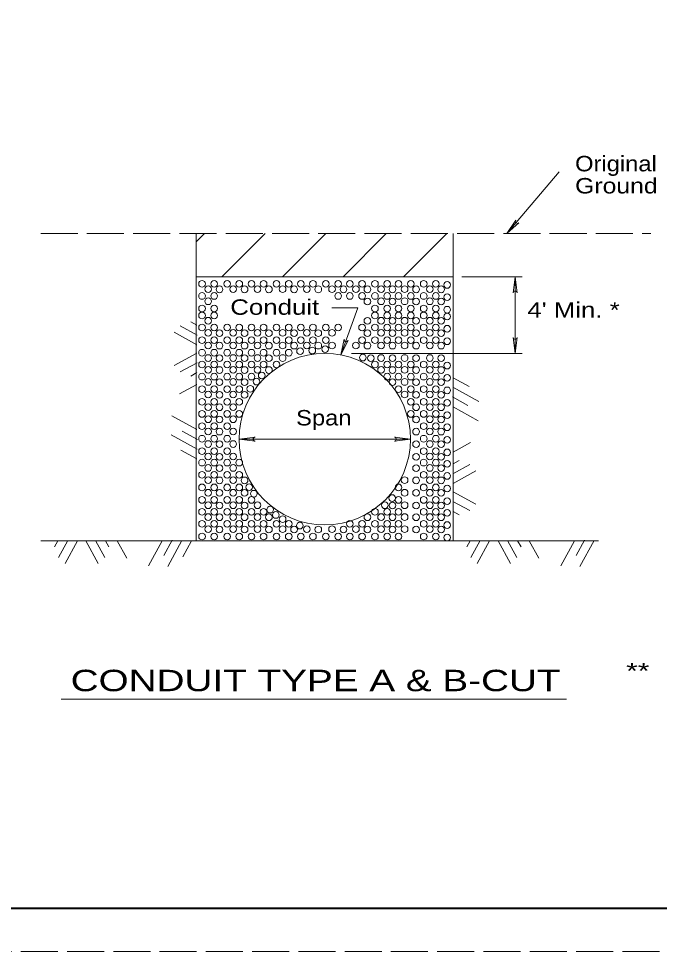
# Model space of a CAD drawing. Extents: x 750.7 to 784.7, y 834.8 to 878.8.
# Drawn here: x 763.05 to 770.52, y 834.78 to 845.67 of the extents above; entities that cross this region are included whole.
import ezdxf

# ---------------------------------------------------------------- set-up
doc = ezdxf.new("R2010")
doc.units = 0
doc.header["$LTSCALE"] = 0.072
doc.linetypes.add('LONG_DASHED', pattern=[7.5, 6, -1.5])
doc.layers.add('1', color=7, linetype='Continuous', lineweight=13)
doc.layers.add('47', color=7, linetype='Continuous', lineweight=13)

msp = doc.modelspace()

# ---------------------------------------------------------------- linework, layer by layer
at = {"layer": '1'}
for p, q in [((768.74392, 843.15875), (769.355, 843.88067)), ((765.11817, 843.15875), (765.11817, 839.5755)), ((765.11817, 843.06225), (765.21467, 843.15875)), ((765.41725, 842.65417), (765.92175, 843.15875)), ((766.12433, 842.65417), (766.62883, 843.15875)), ((766.83142, 842.65417), (767.33592, 843.15875)), ((767.5385, 842.65417), (768.043, 843.15875)), ((768.11817, 843.15875), (768.11817, 839.5755)), ((765.11817, 842.65417), (768.11817, 842.65417)), ((768.21917, 842.65417), (768.9205, 842.65417)), ((768.84058, 841.76058), (768.84058, 842.65417)), ((765.12775, 841.97533), (764.93225, 842.08317)), ((765.12633, 842.09192), (765.055, 842.13125)), ((765.12383, 841.86325), (764.86125, 842.00817)), ((765.12383, 841.76533), (764.86125, 841.62042)), ((766.93208, 841.76058), (768.9205, 841.76058)), ((765.12775, 841.65325), (764.93225, 841.54542)), ((765.12633, 841.53667), (765.055, 841.49733)), ((765.12683, 841.40033), (764.92275, 841.28775)), ((768.11817, 841.47783), (768.30258, 841.37608)), ((768.11425, 841.36575), (768.41542, 841.19958)), ((768.11033, 841.25375), (768.28875, 841.15533)), ((768.11567, 841.13658), (768.40667, 840.976)), ((765.12633, 840.87317), (764.83533, 841.03375)), ((765.13167, 840.756), (764.95325, 840.85442)), ((765.12775, 840.644), (764.82658, 840.81017)), ((765.61817, 840.76083), (767.61817, 840.76083)), ((768.11517, 840.60942), (768.31925, 840.722)), ((765.12383, 840.53192), (764.93942, 840.63367)), ((768.11567, 840.47308), (768.187, 840.51242)), ((768.11425, 840.3565), (768.30975, 840.46433)), ((768.11817, 840.24442), (768.38075, 840.38933)), ((768.11817, 840.1465), (768.38075, 840.00158)), ((768.11425, 840.03442), (768.30975, 839.92658)), ((768.11567, 839.91783), (768.187, 839.8785)), ((763.30275, 839.5755), (769.81092, 839.5755)), ((763.50333, 839.5755), (763.464, 839.50417)), ((763.61992, 839.57692), (763.51208, 839.38142)), ((763.732, 839.573), (763.58708, 839.31042)), ((763.82992, 839.573), (763.97483, 839.31042)), ((763.942, 839.57692), (764.04983, 839.38142)), ((764.05858, 839.5755), (764.09792, 839.50417)), ((764.19492, 839.576), (764.3075, 839.37192)), ((764.72208, 839.5755), (764.5615, 839.2845)), ((764.83925, 839.58083), (764.74083, 839.40242)), ((764.95125, 839.57692), (764.78508, 839.27575)), ((765.06333, 839.573), (764.96158, 839.38858)), ((768.31375, 839.5755), (768.27442, 839.50417)), ((768.43033, 839.57692), (768.3225, 839.38142)), ((768.54242, 839.573), (768.3975, 839.31042)), ((768.64033, 839.573), (768.78525, 839.31042)), ((768.75242, 839.57692), (768.86025, 839.38142)), ((768.869, 839.5755), (768.90833, 839.50417)), ((769.00533, 839.576), (769.11792, 839.37192)), ((769.5325, 839.5755), (769.37192, 839.2845)), ((769.64967, 839.58083), (769.55125, 839.40242)), ((769.76167, 839.57692), (769.5955, 839.27575)), ((763.54108, 837.72625), (769.44075, 837.72625))]:
    msp.add_line(p, q, dxfattribs=at)
at = {"layer": '1', "linetype": 'LONG_DASHED'}
msp.add_line((763.30275, 843.15875), (770.42208, 843.15875), dxfattribs=at)
at = {"layer": '1', "lineweight": 25}
msp.add_line((784.15083, 835.28433), (752.65083, 835.28433), dxfattribs=at)
at = {"layer": '1', "linetype": 'LONG_DASHED'}
msp.add_lwpolyline([(750.65083, 834.78433), (784.65083, 834.78433), (784.65083, 856.78433), (750.65083, 856.78433)], close=True, dxfattribs=at)
at = {"layer": '1', "lineweight": 40}
for points in [[(784.15083, 835.28433), (752.65083, 835.28433), (752.65083, 856.28433), (784.15083, 856.28433)], [(784.15083, 835.28433), (752.65083, 835.28433), (752.65083, 856.28433)]]:
    msp.add_lwpolyline(points, dxfattribs=at)
at = {"layer": '1'}
msp.add_lwpolyline([(766.69908, 842.29425), (767.00342, 842.29425), (766.80425, 841.74333)], dxfattribs=at)
for centre, radius in [((765.18571, 842.57344), 0.03892), ((765.32774, 842.57347), 0.03892), ((765.47863, 842.57344), 0.03892), ((765.62066, 842.57347), 0.03892), ((765.76271, 842.57344), 0.03892), ((765.90474, 842.57347), 0.03892), ((766.05563, 842.57344), 0.03892), ((766.19766, 842.57347), 0.03892), ((766.33871, 842.57344), 0.03892), ((766.48074, 842.57347), 0.03892), ((766.63163, 842.57344), 0.03892), ((766.77366, 842.57347), 0.03892), ((766.9113, 842.57344), 0.03892), ((767.05333, 842.57347), 0.03892), ((767.20421, 842.57344), 0.03892), ((767.34624, 842.57347), 0.03892), ((767.47946, 842.57344), 0.03892), ((767.62149, 842.57347), 0.03892), ((767.77238, 842.57344), 0.03892), ((767.91441, 842.57347), 0.03892), ((768.04758, 842.56014), 0.03892), ((765.18571, 842.43136), 0.03892), ((765.25674, 842.51131), 0.03892), ((765.32774, 842.43139), 0.03892), ((765.38991, 842.50897), 0.03892), ((765.54966, 842.51131), 0.03892), ((765.68283, 842.50897), 0.03892), ((765.83374, 842.51131), 0.03892), ((765.96691, 842.50897), 0.03892), ((766.12666, 842.51131), 0.03892), ((766.25983, 842.50897), 0.03892), ((766.40974, 842.51131), 0.03892), ((766.54291, 842.50897), 0.03892), ((766.70266, 842.51131), 0.03892), ((766.77366, 842.43139), 0.03892), ((766.83583, 842.50897), 0.03892), ((766.9113, 842.43136), 0.03892), ((766.98233, 842.51131), 0.03892), ((767.05333, 842.43139), 0.03892), ((767.11549, 842.50897), 0.03892), ((767.20421, 842.43136), 0.03892), ((767.27524, 842.51131), 0.03892), ((767.34624, 842.43139), 0.03892), ((767.40841, 842.50897), 0.03892), ((767.47946, 842.43136), 0.03892), ((767.55049, 842.51131), 0.03892), ((767.62149, 842.43139), 0.03892), ((767.68366, 842.50897), 0.03892), ((767.77238, 842.43136), 0.03892), ((767.84341, 842.51131), 0.03892), ((767.91441, 842.43139), 0.03892), ((767.97658, 842.50897), 0.03892), ((765.25674, 842.36922), 0.03892), ((767.11549, 842.36689), 0.03892), ((767.27524, 842.36922), 0.03892), ((767.40841, 842.36689), 0.03892), ((767.55049, 842.36922), 0.03892), ((767.68366, 842.36689), 0.03892), ((767.84341, 842.36922), 0.03892), ((767.97658, 842.36689), 0.03892), ((768.04758, 842.41806), 0.03892), ((765.18571, 842.28486), 0.03892), ((765.18571, 842.20494), 0.03892), ((765.32774, 842.28489), 0.03892), ((765.32774, 842.20497), 0.03892), ((767.20421, 842.28486), 0.03892), ((767.20421, 842.20494), 0.03892), ((767.34624, 842.28489), 0.03892), ((767.34624, 842.20497), 0.03892), ((767.47946, 842.28486), 0.03892), ((767.47946, 842.20494), 0.03892), ((767.62149, 842.28489), 0.03892), ((767.62149, 842.20497), 0.03892), ((767.77238, 842.28486), 0.03892), ((767.77238, 842.20494), 0.03892), ((767.91441, 842.28489), 0.03892), ((767.91441, 842.20497), 0.03892), ((768.04758, 842.27156), 0.03892), ((765.25674, 842.14281), 0.03892), ((767.11549, 842.14047), 0.03892), ((767.27524, 842.14281), 0.03892), ((767.40841, 842.14047), 0.03892), ((767.55049, 842.14281), 0.03892), ((767.68366, 842.14047), 0.03892), ((767.84341, 842.14281), 0.03892), ((767.97658, 842.14047), 0.03892), ((768.04758, 842.19164), 0.03892), ((765.18571, 842.06286), 0.03892), ((765.25674, 842.00072), 0.03892), ((765.32774, 842.06289), 0.03892), ((765.38991, 841.99839), 0.03892), ((765.47863, 842.06286), 0.03892), ((765.54966, 842.00072), 0.03892), ((765.62066, 842.06289), 0.03892), ((765.68283, 841.99839), 0.03892), ((765.76271, 842.06286), 0.03892), ((765.83374, 842.00072), 0.03892), ((765.90474, 842.06289), 0.03892), ((765.96691, 841.99839), 0.03892), ((766.05563, 842.06286), 0.03892), ((766.12666, 842.00072), 0.03892), ((766.19766, 842.06289), 0.03892), ((766.25983, 841.99839), 0.03892), ((766.33871, 842.06286), 0.03892), ((766.40974, 842.00072), 0.03892), ((766.48074, 842.06289), 0.03892), ((766.54291, 841.99839), 0.03892), ((766.63163, 842.06286), 0.03892), ((766.70266, 842.00072), 0.03892), ((766.77366, 842.06289), 0.03892), ((767.05333, 842.06289), 0.03892), ((767.11549, 841.99839), 0.03892), ((767.20421, 842.06286), 0.03892), ((767.27524, 842.00072), 0.03892), ((767.34624, 842.06289), 0.03892), ((767.40841, 841.99839), 0.03892), ((767.47946, 842.06286), 0.03892), ((767.55049, 842.00072), 0.03892), ((767.62149, 842.06289), 0.03892), ((767.68366, 841.99839), 0.03892), ((767.77238, 842.06286), 0.03892), ((767.84341, 842.00072), 0.03892), ((767.91441, 842.06289), 0.03892), ((767.97658, 841.99839), 0.03892), ((768.04758, 842.04956), 0.03892), ((765.18571, 841.91636), 0.03892), ((765.32774, 841.91639), 0.03892), ((765.47863, 841.91636), 0.03892), ((765.62066, 841.91639), 0.03892), ((765.76271, 841.91636), 0.03892), ((765.90474, 841.91639), 0.03892), ((766.05563, 841.91636), 0.03892), ((766.19766, 841.91639), 0.03892), ((766.33871, 841.91636), 0.03892), ((766.48074, 841.91639), 0.03892), ((766.63163, 841.91636), 0.03892), ((767.05333, 841.91639), 0.03892), ((767.20421, 841.91636), 0.03892), ((767.34624, 841.91639), 0.03892), ((767.47946, 841.91636), 0.03892), ((767.62149, 841.91639), 0.03892), ((767.77238, 841.91636), 0.03892), ((767.91441, 841.91639), 0.03892), ((768.04758, 841.90306), 0.03892), ((765.18571, 841.76978), 0.03892), ((765.25674, 841.85422), 0.03892), ((765.32774, 841.76981), 0.03892), ((765.38991, 841.85189), 0.03892), ((765.47863, 841.76978), 0.03892), ((765.54966, 841.85422), 0.03892), ((765.62066, 841.76981), 0.03892), ((765.68283, 841.85189), 0.03892), ((765.76271, 841.76978), 0.03892), ((765.83374, 841.85422), 0.03892), ((765.90474, 841.76981), 0.03892), ((765.96691, 841.85189), 0.03892), ((766.05563, 841.76978), 0.03892), ((766.12666, 841.85422), 0.03892), ((766.19766, 841.76981), 0.03892), ((766.25983, 841.85189), 0.03892), ((766.32981, 841.78758), 0.03892), ((766.40974, 841.85422), 0.03892), ((766.47292, 841.79412), 0.03892), ((766.54291, 841.85189), 0.03892), ((766.62375, 841.81187), 0.03892), ((766.70266, 841.85422), 0.03892), ((766.98233, 841.85422), 0.03892), ((767.11549, 841.85189), 0.03892), ((767.27524, 841.85422), 0.03892), ((767.40841, 841.85189), 0.03892), ((767.55049, 841.85422), 0.03892), ((767.68366, 841.85189), 0.03892), ((767.84341, 841.85422), 0.03892), ((767.97658, 841.85189), 0.03892), ((765.25674, 841.70764), 0.03892), ((765.38991, 841.70531), 0.03892), ((765.54966, 841.70764), 0.03892), ((766.61817, 840.76083), 1), ((765.68283, 841.70531), 0.03892), ((765.83374, 841.70764), 0.03892), ((765.96691, 841.70531), 0.03892), ((766.12666, 841.70764), 0.03892), ((767.06222, 841.71203), 0.03892), ((767.15542, 841.70528), 0.03892), ((767.27524, 841.70764), 0.03892), ((767.40841, 841.70531), 0.03892), ((767.55049, 841.70764), 0.03892), ((767.68366, 841.70531), 0.03892), ((767.84341, 841.70764), 0.03892), ((767.97658, 841.70531), 0.03892), ((765.18571, 841.63211), 0.03892), ((765.25674, 841.56997), 0.03892), ((765.32774, 841.63214), 0.03892), ((765.38991, 841.56764), 0.03892), ((765.47863, 841.63211), 0.03892), ((765.54966, 841.56997), 0.03892), ((765.62066, 841.63214), 0.03892), ((765.68283, 841.56764), 0.03892), ((765.76271, 841.63211), 0.03892), ((765.83374, 841.56997), 0.03892), ((765.90474, 841.63214), 0.03892), ((765.96691, 841.56764), 0.03892), ((766.05563, 841.63211), 0.03892), ((767.20421, 841.63211), 0.03892), ((767.27524, 841.56997), 0.03892), ((767.34624, 841.63214), 0.03892), ((767.40841, 841.56764), 0.03892), ((767.47946, 841.63211), 0.03892), ((767.55049, 841.56997), 0.03892), ((767.62149, 841.63214), 0.03892), ((767.68366, 841.56764), 0.03892), ((767.77238, 841.63211), 0.03892), ((767.84341, 841.56997), 0.03892), ((767.91441, 841.63214), 0.03892), ((767.97658, 841.56764), 0.03892), ((768.04758, 841.61881), 0.03892), ((765.18571, 841.49003), 0.03892), ((765.32774, 841.49006), 0.03892), ((765.47863, 841.49003), 0.03892), ((765.62066, 841.49006), 0.03892), ((765.76271, 841.49003), 0.03892), ((765.88251, 841.50338), 0.03892), ((767.34624, 841.49006), 0.03892), ((767.47946, 841.49003), 0.03892), ((767.62149, 841.49006), 0.03892), ((767.77238, 841.49003), 0.03892), ((767.91441, 841.49006), 0.03892), ((768.04758, 841.47672), 0.03892), ((765.18571, 841.34353), 0.03892), ((765.25674, 841.42789), 0.03892), ((765.32774, 841.34356), 0.03892), ((765.38991, 841.42556), 0.03892), ((765.47863, 841.34353), 0.03892), ((765.54966, 841.42789), 0.03892), ((765.62066, 841.34356), 0.03892), ((765.68283, 841.42556), 0.03892), ((765.74942, 841.34794), 0.03892), ((765.82042, 841.43236), 0.03892), ((767.40841, 841.42556), 0.03892), ((767.47946, 841.34353), 0.03892), ((767.55049, 841.42789), 0.03892), ((767.62149, 841.34356), 0.03892), ((767.68366, 841.42556), 0.03892), ((767.77238, 841.34353), 0.03892), ((767.84341, 841.42789), 0.03892), ((767.91441, 841.34356), 0.03892), ((767.97658, 841.42556), 0.03892), ((765.25674, 841.28139), 0.03892), ((765.38991, 841.27906), 0.03892), ((765.54966, 841.28139), 0.03892), ((765.68283, 841.27906), 0.03892), ((767.55049, 841.28139), 0.03892), ((767.68366, 841.27906), 0.03892), ((767.84341, 841.28139), 0.03892), ((767.97658, 841.27906), 0.03892), ((768.04758, 841.33022), 0.03892), ((765.18571, 841.19694), 0.03892), ((765.25674, 841.13481), 0.03892), ((765.32774, 841.19697), 0.03892), ((765.38991, 841.13247), 0.03892), ((765.47863, 841.19694), 0.03892), ((765.54966, 841.13481), 0.03892), ((765.62066, 841.19697), 0.03892), ((767.62149, 841.19697), 0.03892), ((767.68366, 841.13247), 0.03892), ((767.77238, 841.19694), 0.03892), ((767.84341, 841.13481), 0.03892), ((767.91441, 841.19697), 0.03892), ((767.97658, 841.13247), 0.03892), ((768.04758, 841.18364), 0.03892), ((765.18571, 841.05494), 0.03892), ((765.32774, 841.05497), 0.03892), ((765.47863, 841.05494), 0.03892), ((765.62066, 841.05497), 0.03892), ((767.62149, 841.05497), 0.03892), ((767.77238, 841.05494), 0.03892), ((767.91441, 841.05497), 0.03892), ((768.04758, 841.04164), 0.03892), ((765.18571, 840.91286), 0.03892), ((765.25674, 840.99281), 0.03892), ((765.32774, 840.91289), 0.03892), ((765.38991, 840.99047), 0.03892), ((765.47863, 840.91286), 0.03892), ((765.54966, 840.99281), 0.03892), ((767.68366, 840.99047), 0.03892), ((767.77238, 840.91286), 0.03892), ((767.84341, 840.99281), 0.03892), ((767.91441, 840.91289), 0.03892), ((767.97658, 840.99047), 0.03892), ((768.04758, 840.89956), 0.03892), ((765.25674, 840.85072), 0.03892), ((765.38991, 840.84839), 0.03892), ((765.54966, 840.85072), 0.03892), ((767.68366, 840.84839), 0.03892), ((767.84341, 840.85072), 0.03892), ((767.97658, 840.84839), 0.03892), ((765.18571, 840.76636), 0.03892), ((765.25674, 840.70422), 0.03892), ((765.32774, 840.76639), 0.03892), ((765.38991, 840.70189), 0.03892), ((765.47863, 840.76636), 0.03892), ((765.54966, 840.70422), 0.03892), ((767.68366, 840.70189), 0.03892), ((767.77238, 840.76636), 0.03892), ((767.84341, 840.70422), 0.03892), ((767.91441, 840.76639), 0.03892), ((767.97658, 840.70189), 0.03892), ((768.04758, 840.75306), 0.03892), ((765.18571, 840.61978), 0.03892), ((765.32774, 840.61981), 0.03892), ((765.47863, 840.61978), 0.03892), ((767.77238, 840.61978), 0.03892), ((767.91441, 840.61981), 0.03892), ((768.04758, 840.60647), 0.03892), ((765.18571, 840.48661), 0.03892), ((765.25674, 840.55764), 0.03892), ((765.32774, 840.48664), 0.03892), ((765.38991, 840.55531), 0.03892), ((765.47863, 840.48661), 0.03892), ((765.54966, 840.55764), 0.03892), ((765.62066, 840.48664), 0.03892), ((767.68366, 840.55531), 0.03892), ((767.77238, 840.48661), 0.03892), ((767.84341, 840.55764), 0.03892), ((767.91441, 840.48664), 0.03892), ((767.97658, 840.55531), 0.03892), ((768.04758, 840.47331), 0.03892), ((765.25674, 840.42447), 0.03892), ((765.38991, 840.42214), 0.03892), ((765.54966, 840.42447), 0.03892), ((767.68366, 840.42214), 0.03892), ((767.84341, 840.42447), 0.03892), ((767.97658, 840.42214), 0.03892), ((765.18571, 840.34453), 0.03892), ((765.25674, 840.28239), 0.03892), ((765.32774, 840.34456), 0.03892), ((765.38991, 840.28006), 0.03892), ((765.47863, 840.34453), 0.03892), ((765.54966, 840.28239), 0.03892), ((765.62066, 840.34456), 0.03892), ((765.68283, 840.28006), 0.03892), ((767.55049, 840.28239), 0.03892), ((767.68366, 840.28006), 0.03892), ((767.77238, 840.34453), 0.03892), ((767.84341, 840.28239), 0.03892), ((767.91441, 840.34456), 0.03892), ((767.97658, 840.28006), 0.03892), ((768.04758, 840.33122), 0.03892), ((765.18571, 840.19803), 0.03892), ((765.25674, 840.13589), 0.03892), ((765.32774, 840.19806), 0.03892), ((765.47863, 840.19803), 0.03892), ((765.54966, 840.13589), 0.03892), ((765.62066, 840.19806), 0.03892), ((765.73608, 840.20012), 0.03892), ((767.47946, 840.19803), 0.03892), ((767.55049, 840.13589), 0.03892), ((767.77238, 840.19803), 0.03892), ((767.84341, 840.13589), 0.03892), ((767.91441, 840.19806), 0.03892), ((768.04758, 840.18472), 0.03892), ((765.18571, 840.05144), 0.03892), ((765.32774, 840.05147), 0.03892), ((765.38991, 840.13356), 0.03892), ((765.47863, 840.05144), 0.03892), ((765.62066, 840.05147), 0.03892), ((765.68283, 840.13356), 0.03892), ((765.76271, 840.05144), 0.03892), ((765.78933, 840.12462), 0.03892), ((767.40393, 840.07367), 0.03892), ((767.47946, 840.05144), 0.03892), ((767.68366, 840.13356), 0.03892), ((767.77238, 840.05144), 0.03892), ((767.91441, 840.05147), 0.03892), ((767.97658, 840.13356), 0.03892), ((768.04758, 840.03814), 0.03892), ((765.25674, 839.98931), 0.03892), ((765.38991, 839.98697), 0.03892), ((765.54966, 839.98931), 0.03892), ((765.68283, 839.98697), 0.03892), ((765.83374, 839.98931), 0.03892), ((765.98017, 839.93821), 0.03892), ((767.3196, 839.98926), 0.03892), ((767.40841, 839.98697), 0.03892), ((767.55049, 839.98931), 0.03892), ((767.68366, 839.98697), 0.03892), ((767.84341, 839.98931), 0.03892), ((767.97658, 839.98697), 0.03892), ((765.18571, 839.91378), 0.03892), ((765.25674, 839.85164), 0.03892), ((765.32774, 839.91381), 0.03892), ((765.38991, 839.84931), 0.03892), ((765.47863, 839.91378), 0.03892), ((765.54966, 839.85164), 0.03892), ((765.62066, 839.91381), 0.03892), ((765.68283, 839.84931), 0.03892), ((765.76271, 839.91378), 0.03892), ((765.83374, 839.85164), 0.03892), ((765.90474, 839.91381), 0.03892), ((765.96691, 839.84931), 0.03892), ((766.04675, 839.87604), 0.03892), ((766.12667, 839.82712), 0.03892), ((767.11549, 839.84931), 0.03892), ((767.20421, 839.91378), 0.03892), ((767.27524, 839.85164), 0.03892), ((767.34624, 839.91381), 0.03892), ((767.40841, 839.84931), 0.03892), ((767.47946, 839.91378), 0.03892), ((767.55049, 839.85164), 0.03892), ((767.68366, 839.84931), 0.03892), ((767.77238, 839.91378), 0.03892), ((767.84341, 839.85164), 0.03892), ((767.91441, 839.91381), 0.03892), ((767.97658, 839.84931), 0.03892), ((768.04758, 839.90047), 0.03892), ((765.18571, 839.77169), 0.03892), ((765.25674, 839.70956), 0.03892), ((765.32774, 839.77172), 0.03892), ((765.38991, 839.70722), 0.03892), ((765.47863, 839.77169), 0.03892), ((765.54966, 839.70956), 0.03892), ((765.62066, 839.77172), 0.03892), ((765.68283, 839.70722), 0.03892), ((765.76271, 839.77169), 0.03892), ((765.83374, 839.70956), 0.03892), ((765.90474, 839.77172), 0.03892), ((765.96691, 839.70722), 0.03892), ((766.05563, 839.77169), 0.03892), ((766.12666, 839.70956), 0.03892), ((766.19766, 839.77172), 0.03892), ((766.25983, 839.70722), 0.03892), ((766.32642, 839.75171), 0.03892), ((766.40974, 839.70956), 0.03892), ((766.54291, 839.70722), 0.03892), ((766.70266, 839.70956), 0.03892), ((766.83583, 839.70722), 0.03892), ((766.9113, 839.77169), 0.03892), ((766.98233, 839.70956), 0.03892), ((767.05333, 839.77172), 0.03892), ((767.11549, 839.70722), 0.03892), ((767.20421, 839.77169), 0.03892), ((767.27524, 839.70956), 0.03892), ((767.34624, 839.77172), 0.03892), ((767.40841, 839.70722), 0.03892), ((767.47946, 839.77169), 0.03892), ((767.55049, 839.70956), 0.03892), ((767.68366, 839.70722), 0.03892), ((767.77238, 839.77169), 0.03892), ((767.84341, 839.70956), 0.03892), ((767.91441, 839.77172), 0.03892), ((767.97658, 839.70722), 0.03892), ((768.04758, 839.75839), 0.03892), ((765.18571, 839.62519), 0.03892), ((765.32774, 839.62522), 0.03892), ((765.47863, 839.62519), 0.03892), ((765.62066, 839.62522), 0.03892), ((765.76271, 839.62519), 0.03892), ((765.90474, 839.62522), 0.03892), ((766.05563, 839.62519), 0.03892), ((766.19766, 839.62522), 0.03892), ((766.33871, 839.62519), 0.03892), ((766.48074, 839.62522), 0.03892), ((766.63163, 839.62519), 0.03892), ((766.77366, 839.62522), 0.03892), ((766.9113, 839.62519), 0.03892), ((767.05333, 839.62522), 0.03892), ((767.20421, 839.62519), 0.03892), ((767.34624, 839.62522), 0.03892), ((767.47946, 839.62519), 0.03892), ((767.77238, 839.62519), 0.03892), ((767.91441, 839.62522), 0.03892), ((768.04758, 839.61189), 0.03892)]:
    msp.add_circle(centre, radius, dxfattribs=at)
at = {"layer": '47'}
for points in [[(768.88292, 843.28675), (768.74392, 843.15875), (768.84717, 843.317)], [(768.81717, 842.46667), (768.84058, 842.65417), (768.864, 842.46667)], [(766.89, 841.91167), (766.80425, 841.74333), (766.846, 841.92767)], [(768.864, 841.94808), (768.84058, 841.76058), (768.81717, 841.94808)], [(765.80567, 840.73742), (765.61817, 840.76083), (765.80567, 840.78425)], [(767.43067, 840.78425), (767.61817, 840.76083), (767.43067, 840.73742)]]:
    msp.add_lwpolyline(points, dxfattribs=at)
for centre, start, end in [((768.86506, 843.30187), 139.75297, 319.75297), ((768.84059, 842.46666), 0, 180), ((766.86799, 841.91967), 160.12536, 340.12536), ((768.84058, 841.94809), 180, 0), ((765.80567, 840.76084), 90, 270), ((767.43066, 840.76083), 270, 90)]:
    msp.add_arc(centre, 0.02342, start, end, dxfattribs=at)

# ---------------------------------------------------------------- texts
at = {"layer": '1'}
for s, height, width, p in [('Original', 0.18, 1.15, (769.53942, 843.88583)), ('Ground', 0.18, 1.2, (769.53942, 843.62783)), ('Conduit', 0.18, 1.25, (765.51592, 842.21192)), ("4' Min. *", 0.18, 1.25, (768.98267, 842.17917)), ('Span', 0.18, 1.15, (766.28358, 840.92067)), ('**', 0.18, 1.45, (770.13517, 837.96808)), ('CONDUIT TYPE A & B-CUT', 0.25, 1.35, (763.6525, 837.81983))]:
    msp.add_text(s, height=height, dxfattribs=dict(at, width=width)).set_placement(p)

doc.saveas('drawing.dxf')
